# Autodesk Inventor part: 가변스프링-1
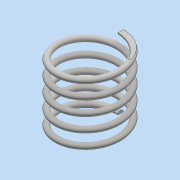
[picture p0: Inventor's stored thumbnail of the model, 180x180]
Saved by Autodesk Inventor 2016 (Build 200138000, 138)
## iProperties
Created: 2015-11
Part Number: 가변스프링-1
Material: 일반
Document SubType Name: Modeling
Designer: Administrator
Density: 1 g/cm^3
Appearance: 기본값
Mass: 1.07438 g
Surface Area: 21.7379 cm^2
Volume: 1.07438 cm^3
Author: Administrator
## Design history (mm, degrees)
sketch "스케치2"
  geometry: L1 (0, 0)-(11, 0); L2 (11, 0)-(11, 40.245); L3 (11, 40.245)-(0, 40.245); L4 (0, 40.245)-(0, 0); C1 r 1 at (11, 0)
  constraints: 8 end point, 2 parallel, 1 centre point, 1 coincident, 1 horizontal, 1 perpendicular
  dimensions: "d0" = 2 diameter of C1; "d1" = 22 diameter of L2 L4; "d2" = 40.2455 distance between parallel lines of L3 L1 (derived)
feature "코일1" sketch "스케치2" pitch "d3" = 10; turns "d5" = 5; dims "d4" = 40.2455 (= d2), "d6" = 0, angle "d7" = 90 deg, angle "d8" = 90 deg, "d9" = 0, "d10" = 0
sketch "스케치3"
  geometry: L1 (0, 12)-(0, 10) reference; 1 further point
  constraints: 1 vertical alignment
extrude "돌출1" cut sketch "스케치3" distance "d11" = 10; taper "d12" = 0 deg
node "작업 평면1"
sketch "스케치4"
  geometry: L1 (0, -1)-(0, 1) reference; 1 further point
  constraints: 1 vertical alignment
extrude "돌출2" cut sketch "스케치4" distance "d13" = 10; taper "d14" = 0 deg
node "솔리드1"
node "절단 모서리 투영1"
node "절단 모서리 투영2"
